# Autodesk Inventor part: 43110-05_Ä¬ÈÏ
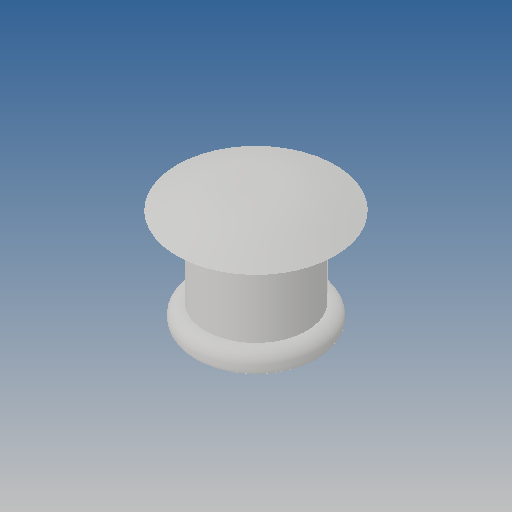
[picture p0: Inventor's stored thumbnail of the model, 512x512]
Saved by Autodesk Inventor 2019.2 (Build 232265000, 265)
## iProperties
Created: 2010-06
Part Number: 43110-05_Ä¬ÈÏ
Material: Ogólny
Document SubType Name: Modeling
Designer: CADENGINEERING4
Density: 1 g/cm^3
Appearance: Domyślna
Author: CADENGINEERING4
Revision Number: ÈÎºÎ
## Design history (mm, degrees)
feature "NONE"
node "Bryła1"
